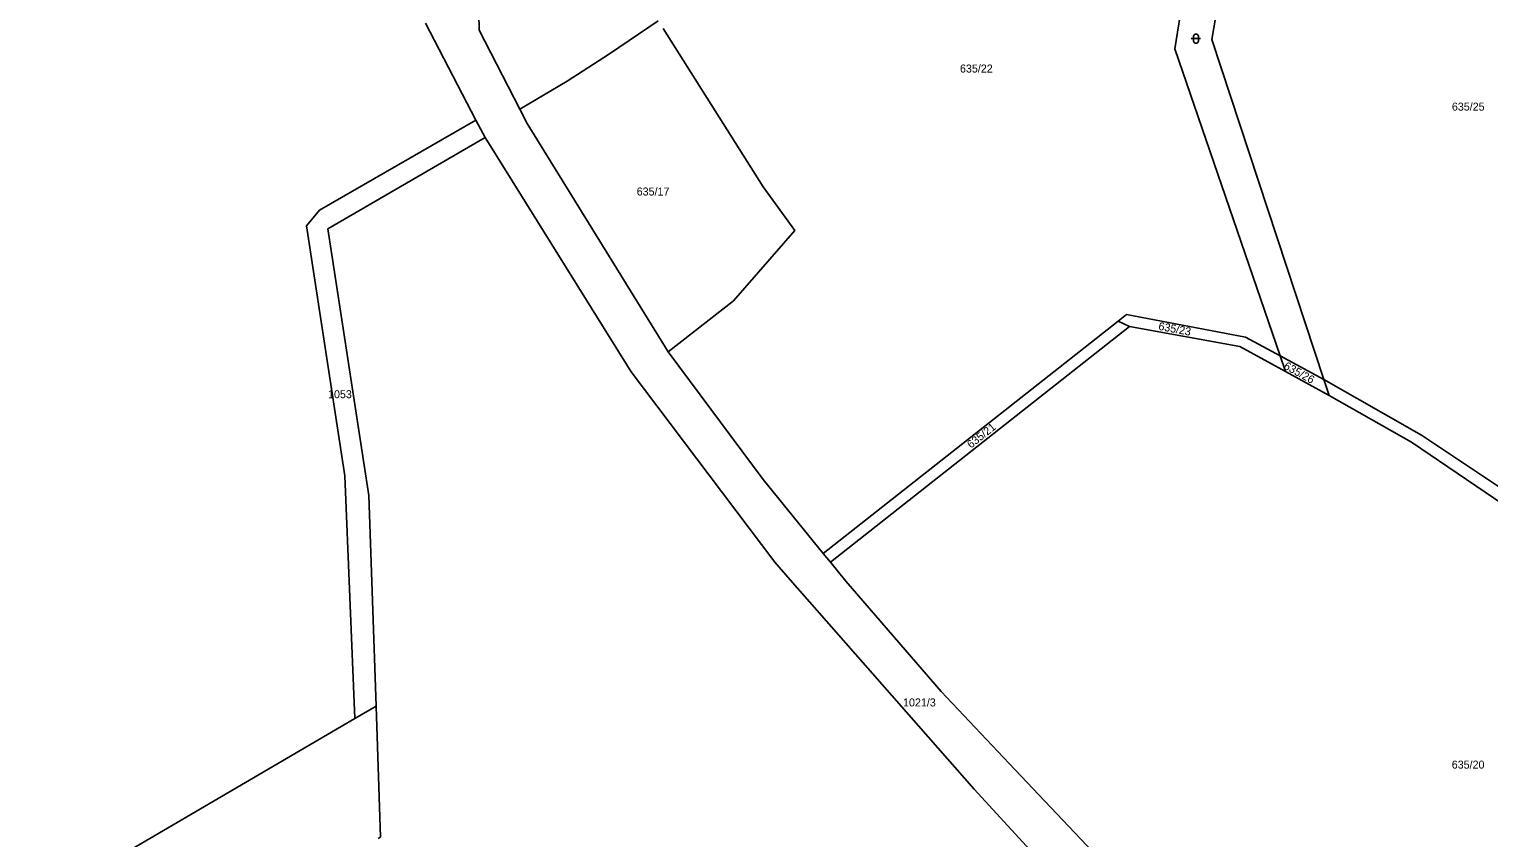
# Model space of a CAD drawing. Extents: x -801907 to -800293, y -1016964 to -1015684.
# Drawn here: x -800902.2 to -800592.1, y -1016304.7 to -1016132.8 of the extents above; entities that cross this region are included whole.
import ezdxf

# ---------------------------------------------------------------- set-up
doc = ezdxf.new("R2010")
doc.units = 0
for name, color, linetype in [('Default', 7, 'Continuous'), ('KN_HRANICE', 7, 'Continuous'), ('KN_KULTURY', 7, 'Continuous'), ('KN_PARCELY', 7, 'Continuous')]:
    doc.layers.add(name, color=color, linetype=linetype)

# ---------------------------------------------------------------- blocks, each defined once
blk = doc.blocks.new('316')
at = {"layer": 'Default'}
for points in [[(-1, 1), (0.27, 1), (1, 1)], [(-0.5, 1.5), (-0.4, 1.79), (-0.15, 1.97), (0.16, 1.97), (0.41, 1.79), (0.51, 1.5), (0.51, 0.5), (0.41, 0.21), (0.16, 0.03), (-0.15, 0.03), (-0.4, 0.21), (-0.5, 0.5), (-0.5, 1.5)]]:
    blk.add_lwpolyline(points, dxfattribs=at)

msp = doc.modelspace()

# ---------------------------------------------------------------- linework, layer by layer
at = {"layer": 'KN_HRANICE'}
for p, q in [((-800649.62, -1016080.7), (-800658.77, -1016137)), ((-800642.01, -1016082.06), (-800650.89, -1016135.02)), ((-800806.9, -1016116.78), (-800806.54, -1016133.07)), ((-800768.52, -1016131.08), (-800778.84, -1016138.06)), ((-800817.98, -1016131.56), (-800807.23, -1016152.14)), ((-800806.54, -1016133.07), (-800797.93, -1016149.82)), ((-800767.44, -1016132.7), (-800746.19, -1016166.34)), ((-800658.77, -1016137), (-800636.42, -1016202.22)), ((-800650.89, -1016135.02), (-800627.11, -1016207.26)), ((-800778.84, -1016138.06), (-800787.87, -1016143.9)), ((-800787.87, -1016143.9), (-800797.93, -1016149.82)), ((-800797.93, -1016149.82), (-800796.36, -1016152.89)), ((-800840.49, -1016171.3), (-800807.23, -1016152.14)), ((-800807.23, -1016152.14), (-800805.29, -1016155.85)), ((-800796.36, -1016152.89), (-800766.37, -1016201.36)), ((-800805.29, -1016155.85), (-800838.71, -1016175.29)), ((-800805.29, -1016155.85), (-800774.29, -1016205.68)), ((-800746.19, -1016166.34), (-800739.51, -1016175.64)), ((-800840.49, -1016171.3), (-800843.21, -1016174.61)), ((-800843.21, -1016174.61), (-800835.06, -1016227.76)), ((-800838.71, -1016175.29), (-800829.97, -1016231.91)), ((-800739.51, -1016175.64), (-800752.56, -1016190.54)), ((-800752.56, -1016190.54), (-800766.37, -1016201.36)), ((-800670.83, -1016194.89), (-800733.45, -1016244.24)), ((-800668.38, -1016196), (-800731.92, -1016246.12)), ((-800669.02, -1016193.47), (-800670.83, -1016194.89)), ((-800670.83, -1016194.89), (-800668.38, -1016196)), ((-800643.75, -1016198.25), (-800669.02, -1016193.47)), ((-800668.38, -1016196), (-800644.93, -1016200.27)), ((-800636.42, -1016202.22), (-800643.75, -1016198.25)), ((-800766.37, -1016201.36), (-800746.21, -1016228.54)), ((-800644.93, -1016200.27), (-800635.27, -1016205.57)), ((-800627.11, -1016207.26), (-800636.42, -1016202.22)), ((-800636.42, -1016202.22), (-800635.27, -1016205.57)), ((-800774.29, -1016205.68), (-800743.77, -1016246.11)), ((-800626, -1016210.64), (-800635.27, -1016205.57)), ((-800606.39, -1016219.1), (-800627.11, -1016207.26)), ((-800627.11, -1016207.26), (-800626, -1016210.64)), ((-800626, -1016210.64), (-800608.51, -1016220.58)), ((-800608.51, -1016220.58), (-800576, -1016242.64)), ((-800577.22, -1016238.6), (-800606.39, -1016219.1)), ((-800835.06, -1016227.76), (-800832.94, -1016279.31)), ((-800746.21, -1016228.54), (-800733.45, -1016244.24)), ((-800829.97, -1016231.91), (-800828.45, -1016276.68)), ((-800733.45, -1016244.24), (-800731.92, -1016246.12)), ((-800743.77, -1016246.11), (-800740.47, -1016249.87)), ((-800731.92, -1016246.12), (-800728.65, -1016250.14)), ((-800740.47, -1016249.87), (-800701.43, -1016294.3)), ((-800728.65, -1016250.14), (-800708.39, -1016273.55)), ((-800708.39, -1016273.55), (-800693.94, -1016288.84)), ((-800832.94, -1016279.31), (-800828.45, -1016276.68)), ((-800828.45, -1016276.68), (-800827.51, -1016304.5)), ((-800902.15, -1016319.78), (-800832.94, -1016279.31)), ((-800693.94, -1016288.84), (-800661.88, -1016322.76)), ((-800701.43, -1016294.3), (-800671.28, -1016327.06)), ((-800827.51, -1016304.5), (-800828.01, -1016304.81))]:
    msp.add_line(p, q, dxfattribs=at)

# ---------------------------------------------------------------- block references
at = {"layer": 'KN_KULTURY'}
msp.add_blockref('316', (-800654.28, -1016135.85), dxfattribs=at)

# ---------------------------------------------------------------- texts
at = {"layer": 'KN_PARCELY'}
for s, p in [('635/22', (-800704.41, -1016142.05)), ('635/25', (-800599.91, -1016150.14)), ('635/17', (-800773.09, -1016168.18)), ('1053', (-800838.66, -1016211.25)), ('1021/3', (-800716.51, -1016276.74)), ('635/20', (-800599.94, -1016289.95))]:
    msp.add_text(s, height=1.7, dxfattribs=at).set_placement(p)
for s, rotation, p in [('635/23', 349.332, (-800662.35, -1016196.7)), ('635/26', 331.17, (-800635.79, -1016204.89)), ('635/21', 38.388, (-800702.08, -1016221.99))]:
    msp.add_text(s, height=1.7, rotation=rotation, dxfattribs=at).set_placement(p)

doc.saveas('drawing.dxf')
